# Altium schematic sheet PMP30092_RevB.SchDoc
size 431 x 279 mm; Date: Not shown in title block; ApprovedBy: Not shown in title block; CheckedBy: Not shown in title block; Author: Not shown in title block; CompanyName: Not shown in title block; Engineer: Not shown in title block; Organization: Not shown in title block; Address1: Not shown in title block; Address2: Not shown in title block; Address3: Not shown in title block; Address4: Not shown in title block; DocumentNumber: 1; Revision: Use project parameter SCH_Rev; SheetNumber: 2; SheetTotal: 3; PageSetup: Record=PageOptions¦CenterHorizontal=True¦CenterVertical=True¦PrintScale=1.00¦XCorrection=1.00¦YCorrection=1.00¦PrintKind=0¦BorderSize=5000000¦LeftOffset=0¦BottomOffset=0¦Orientation=2¦PaperLength=1000¦PaperWidth=1000¦Scale=100¦PaperSource=15¦PrintQuality=600¦MediaType=1¦DitherType=10¦PaperKind=Letter¦PrintScaleMode=1
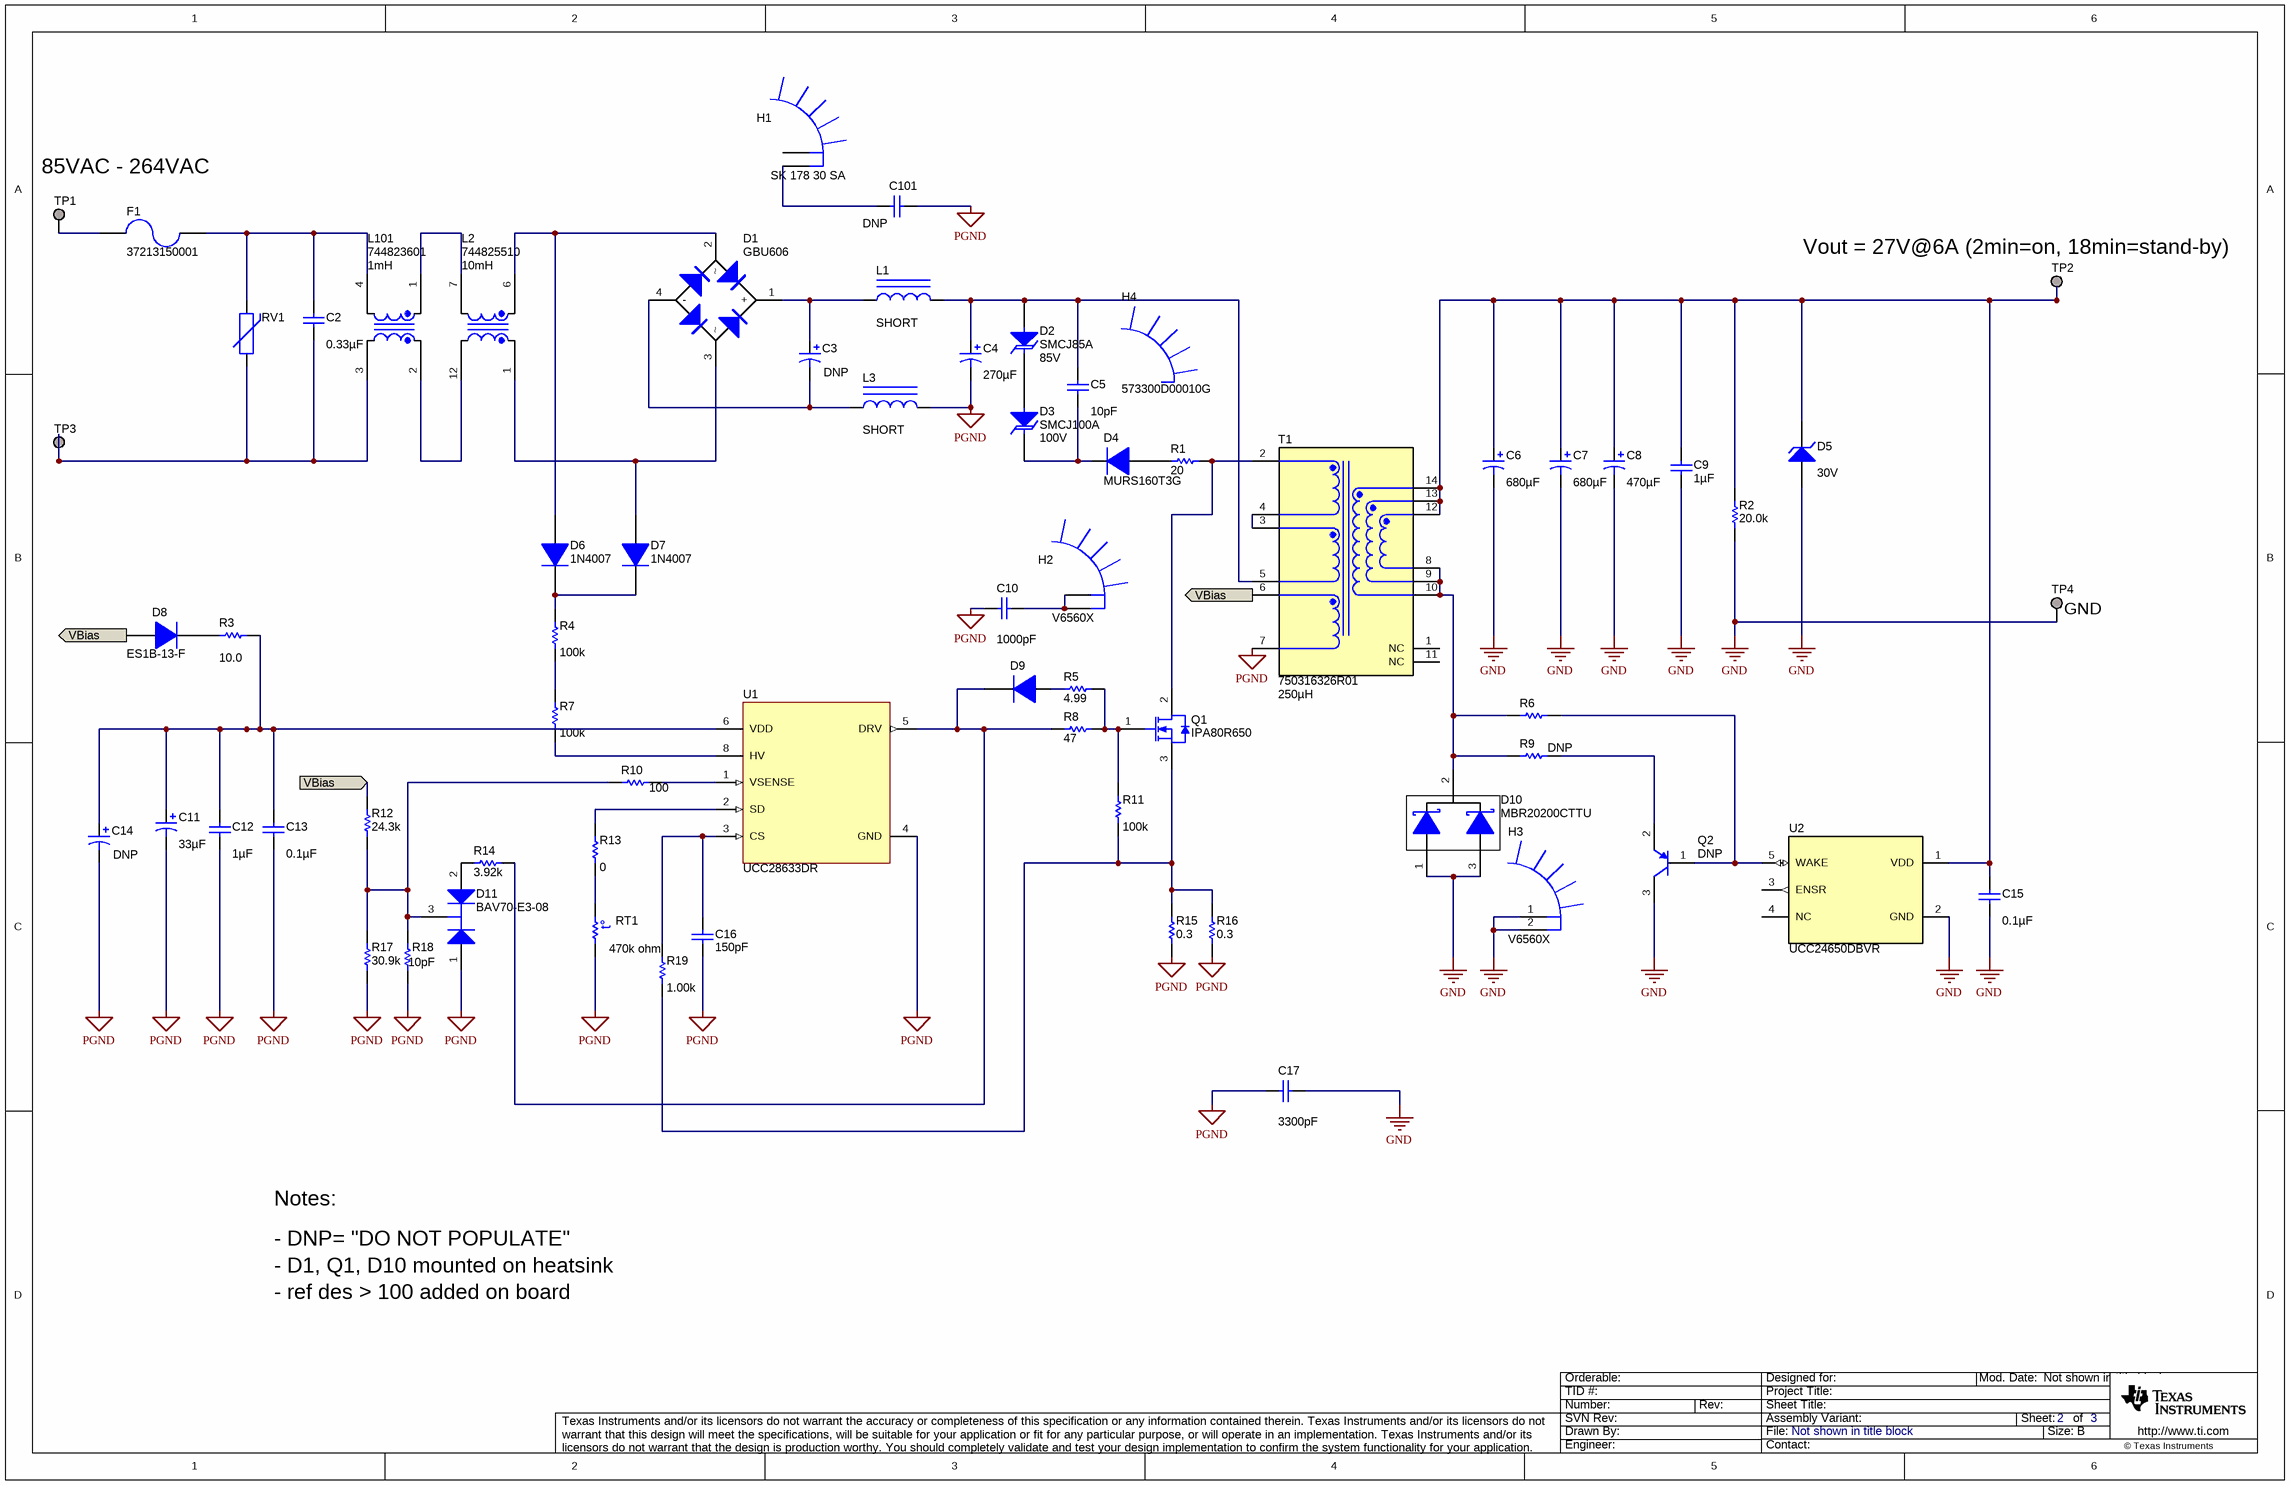
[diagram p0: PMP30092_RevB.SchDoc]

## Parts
C2  ValueDisplayed: 0.33µF  [B32922_14.5mm]  (hidden comment: B32922C3334M)
C3  DNP  [CY_1250x2000]
C4  ValueDisplayed: 270µF  [LGW_3000x3500]  (hidden comment: LGW2G271MELB35)
C5  ValueDisplayed: 10pF  [1206]  (hidden comment: 12062A100JAT2A)
C6  ValueDisplayed: 680µF  [HW_1000x2000]  (hidden comment: UHW1V681MPD6)
C7  ValueDisplayed: 680µF  [HW_1000x2000]  (hidden comment: UHW1V681MPD6)
C8  ValueDisplayed: 470µF  [HW_1000x1600]  (hidden comment: UHW1V471MPD)
C9  ValueDisplayed: 1µF  [1206_180]  (hidden comment: C3216X7R1H105K160AB)
C10  ValueDisplayed: 1000pF  [1206]  (hidden comment: GRM31BR72J102KW01L)
C11  ValueDisplayed: 33µF  [SM_RADIAL_E]  (hidden comment: EEE-FC1V330P)
C12  ValueDisplayed: 1µF  [1206]  (hidden comment: C1206C105K3RACTU)
C13  ValueDisplayed: 0.1µF  [0603]  (hidden comment: 06035C104KAT2A)
C14  value DNP  [SM_RADIAL_E]  (hidden comment: Used in BOM report)
C15  ValueDisplayed: 0.1µF  [0805_HV]  (hidden comment: 08055C104KAT2A)
C16  ValueDisplayed: 150pF  [0603]  (hidden comment: C0603C151J5GACTU)
C17  ValueDisplayed: 3300pF  [KX_1000x700]  (hidden comment: DE1E3KX332MN4AP01F)
C101  value DNP  [1206]  (hidden comment: GRM31BR72J102KW01L)
D1  GBU606  [GBU]
D2  SMCJ85A  value 85V  [SMC]
D3  SMCJ100A  value 100V  [SMC]
D4  MURS160T3G  [SMB]
D5  value 30V  [SOD-123]  (hidden comment: MMSZ5255B-7-F)
D6  1N4007  [DO-41]
D7  1N4007  [DO-41]
D8  ES1B-13-F  [SMA]
D9  BAS316,115  [sod-323]  (value not drawn)
D10  MBR20200CTTU  [TO-220AB]
D11  BAV70-E3-08  [SOT-23]
F1  37213150001  [FUSE_372]
H1  SK 178 30 SA
H2  V6560X  [ASMN_V6560X]
H3  V6560X  [ASMN_V6560X]
H4  573300D00010G  [HEATSINK_573300D00010G]
L1  ValueDisplayed: SHORT  [DO5040H]  (hidden comment: DO5040H-473MLB)
L2  744825510  ValueDisplayed: 10mH  [WE-CMB_XL]
L3  ValueDisplayed: SHORT  [DO5040H]  (hidden comment: DO5040H-473MLB)
L101  744823601  value 1mH  [WE-CMB_M]
Q1  IPA80R650  [TO-220AB]
Q2  DNP  [SOT-23]
R1  ValueDisplayed: 20  [2512]  (hidden comment: CRCW251220R0JNEG)
R2  ValueDisplayed: 20.0k  [0603]  (hidden comment: RC0603FR-0720KL)
R3  ValueDisplayed: 10.0  [0805_HV]  (hidden comment: CRCW080510R0FKEA)
R4  ValueDisplayed: 100k  [1206]  (hidden comment: CRCW1206100KFKEA)
R5  ValueDisplayed: 4.99  [0805_HV]  (hidden comment: RC0805FR-074R99L)
R6  CRCW08050000Z0EA  [0805_HV]  (value not drawn)
R7  ValueDisplayed: 100k  [1206]  (hidden comment: CRCW1206100KFKEA)
R8  ValueDisplayed: 47  [0805_HV]  (hidden comment: ERJ-6GEYJ470V)
R9  DNP  [0805_HV]
R10  ValueDisplayed: 100  [0603]  (hidden comment: CRCW0603100RFKEA)
R11  ValueDisplayed: 100k  [0603]  (hidden comment: CRCW0603100KFKEA)
R12  ValueDisplayed: 24.3k  [0603]  (hidden comment: CRCW060324K3FKEA)
R13  ValueDisplayed: 0  [0603]  (hidden comment: CRCW06030000Z0EA)
R14  ValueDisplayed: 3.92k  [0603]  (hidden comment: CRCW06033K92FKEA)
R15  ValueDisplayed: 0.3  [2512]  (hidden comment: CSRN2512FKR300)
R16  ValueDisplayed: 0.3  [2512]  (hidden comment: CSRN2512FKR300)
R17  ValueDisplayed: 30.9k  [0603]  (hidden comment: CRCW060330K9FKEA)
R18  value 10pF  [0603]  (hidden comment: Used in BOM report)
R19  ValueDisplayed: 1.00k  [0603]  (hidden comment: CRCW06031K00FKEA)
RT1  value 470k ohm  [0603]  (hidden comment: NCP18WM474J03RB)
RV1  B72214S0271K101  [VAR_B72214S0271]  (value not drawn)
T1  750316326R01  ValueDisplayed: 250µH  [Wurth_750316326]
TP1  Suggest using a net name here  [Keystone1503-2]  (value not drawn)
TP2  Suggest using a net name here  [Keystone1503-2]  (value not drawn)
TP3  Suggest using a net name here  [Keystone1503-2]  (value not drawn)
TP4  Suggest using a net name here  [Keystone1503-2]  (value not drawn)
U1  UCC28633DR  [D0007A_N]
U2  UCC24650DBVR  [DBV0005A_N]

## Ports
VBias, VBias (in)

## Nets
GND: C6.2(-) C7.2(-) C8.2(-) C9.2 C15.2 C17.1 D5.2(A) D10.1(A) D10.3(A) H3.1 H3.2 Q2.3(C) R2.1 TP4.1 U2.2(GND)
PGND: C4.2(-) C10.2 C11.2(-) C12.2 C13.2 C14.2(-) C16.2 C17.2 C101.1 D11.1(A) L3.2 R15.1 R16.1 R17.1 R18.1 RT1.1 T1.7 U1.4(GND)
VBias: D8.2(A) R12.2 T1.6 ; port VBias
NetC2_1: C2.1 F1.1 L101.4 RV1.2
NetC2_2: C2.2 L101.3 RV1.1 TP3.1
NetC3_1: C3.1(+) D1.1(+) L1.1
NetC3_2: C3.2(-) D1.4(-) L3.1
NetC4_1: C4.1(+) C5.1 D2.2(A) L1.2 T1.5
NetC5_2: C5.2 D3.1(K) D4.1(K)
NetC6_1: C6.1(+) C7.1(+) C8.1(+) C9.1 C15.1 D5.1(K) R2.2 T1.12 T1.13 T1.14 TP2.1 U2.1(VDD)
NetC10_1: C10.1 H2.1 H2.2
NetC11_1: C11.1(+) C12.1 C13.1 C14.1(+) R3.2 U1.6(VDD)
NetC16_1: C16.1 R19.2 U1.3(CS)
NetC101_2: C101.2 H1.2
NetD1_2: D1.2 D6.2(A) L2.6
NetD1_3: D1.3 D7.2(A) L2.1
NetD2_1: D2.1(K) D3.2(A)
NetD4_2: D4.2(A) R1.1
NetD6_1: D6.1(K) D7.1(K) R4.2
NetD8_1: D8.1(K) R3.1
NetD9_1: D9.1(K) R8.1 R14.2 U1.5(DRV)
NetD9_2: D9.2(A) R5.1
NetD10_2: D10.2(K) R6.1 R9.1 T1.8 T1.9 T1.10
NetD11_2: D11.2(K) R14.1
NetD11_3: D11.3(C) R10.1 R12.1 R17.2 R18.2
NetF1_2: F1.2 TP1.1
NetL2_7: L2.7 L101.1
NetL2_12: L2.12 L101.2
NetQ1_1: Q1.1(G) R5.2 R8.2 R11.2
NetQ1_2: Q1.2(D) R1.2 T1.2
NetQ1_3: Q1.3(S) R11.1 R15.2 R16.2 R19.1
NetQ2_1: Q2.1(B) R6.2 U2.5(WAKE)
NetQ2_2: Q2.2(E) R9.2
NetR4_1: R4.1 R7.2
NetR7_1: R7.1 U1.8(HV)
NetR10_2: R10.2 U1.1(VSENSE)
NetR13_1: R13.1 RT1.2
NetR13_2: R13.2 U1.2(SD)
NetT1_3: T1.3 T1.4

Not connected (* = marked no-connect by the designer): H1 1; T1 1(NC) 11(NC); U2 3(ENSR) 4(NC)

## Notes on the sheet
- 85VAC - 264VAC
- (near TP2) Vout = 27V@6A (2min=on, 18min=stand-by)
- (near T1) Nsec
- (near TP4) GND
- Notes:
- - DNP= "DO NOT POPULATE"
- - D1, Q1, D10 mounted on heatsink
- - ref des > 100 added on board

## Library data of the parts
C2 = B32922C3334M: CAP, Film, 0.33 µF, 630 V, +/- 20%, TH; Manufacturer: TDK; Polarized: N; CompType: Capacitor; Value: 0.33uF; U/M: EA; Cap_F: 0.00000033; Tolerance_%: 20; Value1: Unknown; VDC_V: 630; Value2: 630V; TaMax_C: 110; AEC Category: Q200
C3 = UCY2G270MHD1TO: CAP, AL, 27 µF, 400 V, +/- 20%, TH; Manufacturer: Nichicon; Polarized: Y; CompType: Capacitor; U/M: EA; Cap_F: 0.000027; Tolerance_%: 20; Value1: Unknown; VDC_V: 400; Value2: 400V; IRMS_A: 0.36; TaMin_C: -40; TaMax_C: 105; Cap_Case: 12.5x20; AEC Category: Q200; AEC Qualified: N; Lifetime @ Temp.: 12000 Hrs @ 105°C; Polarization: Polar; Ripple Current: 235mA @ 120Hz
C4 = LGW2G271MELB35: CAP, AL, 270 µF, 400 V, +/- 20%, TH; Manufacturer: Nichicon; Polarized: Y; CompType: Capacitor; Value: 270uF; U/M: EA; Cap_F: 0.00027; Tolerance_%: 20; Value1: Unknown; VDC_V: 400; Value2: 400V; IRMS_A: 2.12; TaMin_C: -25; TaMax_C: 105; Cap_Case: 30x35mm; AEC Category: Q200; AEC Qualified: N
C5 = 12062A100JAT2A: CAP, CERM, 10 pF, 200 V, +/- 5%, C0G/NP0, 1206; Manufacturer: AVX; Polarized: N; CompType: Capacitor; Value: 10pF; U/M: EA; Cap_F: 0.00000000001; Tolerance_%: 5; Value1: Unknown; VDC_V: 200; Value2: 200V; TaMin_C: -55; TaMax_C: 125; AEC Category: Q200
C6 C7 = UHW1V681MPD6: CAP, AL, 680 µF, 35 V, +/- 20%, 0.019 ohm, TH; Manufacturer: Nichicon; Polarized: Y; CompType: Capacitor; Value: 680uF; U/M: EA; Cap_F: 0.00068; Tolerance_%: 20; VDC_V: 35; Value2: 35V; ESR_ohm: 0.019; IRMS_A: 2.5; TaMin_C: -40; TaMax_C: 105; Cap_Case: 10x20; AEC Category: Q200; AEC Qualified: N
C8 = UHW1V471MPD: CAP, AL, 470 µF, 35 V, +/- 20%, 0.03 ohm, TH; Manufacturer: Nichicon; Polarized: Y; CompType: Capacitor; Value: 470uF; U/M: EA; Cap_F: 0.00047; Tolerance_%: 20; VDC_V: 35; Value2: 35V; ESR_ohm: 0.03; IRMS_A: 2; TaMin_C: -40; TaMax_C: 105; Cap_Case: 10x16mm; AEC Category: Q200; AEC Qualified: N
C9 = C3216X7R1H105K160AB: CAP, CERM, 1 µF, 50 V, +/- 10%, X7R, 1206; Manufacturer: TDK; Polarized: N; CompType: Capacitor; Value: 1uF; U/M: EA; Cap_F: 0.000001; Tolerance_%: 10; ESR_ohm: 0.009289; Value1: 0.009289 ohm; VDC_V: 50; Value2: 50V; IRMS_A: 2.38446; TaMin_C: -55; TaMax_C: 125; SizeArea_mm2: 5.12; SizeAreaWB_mm2: 10.92; SizeX_mm: 3.2; SizeY_mm: 1.6; SizeZ_mm: 1.8; AEC Category: Q200
C10 = GRM31BR72J102KW01L: CAP, CERM, 1000 pF, 630 V, +/- 10%, X7R, 1206; Manufacturer: MuRata; Polarized: N; CompType: Capacitor; Value: 1000pF; U/M: EA; Cap_F: 0.000000001; Tolerance_%: 10; Value1: Unknown; VDC_V: 630; Value2: 630V; TaMin_C: -55; TaMax_C: 125; SizeArea_mm2: 5.12; SizeAreaWB_mm2: 10.92; SizeX_mm: 3.2; SizeY_mm: 1.6; SizeZ_mm: 1.35; AEC Category: Q200
C11 = EEE-FC1V330P: CAP, AL, 33 µF, 35 V, +/- 20%, 0.4 ohm, SMD; Manufacturer: Panasonic; Polarized: Y; CompType: Capacitor; Value: 33uF; U/M: EA; Cap_F: 0.000033; Tolerance_%: 20; Value1: 0.4 ohm; VDC_V: 35; Value2: 35V; ESR_ohm: 0.4; IRMS_A: 0.15; TaMin_C: -40; TaMax_C: 105; Cap_Case: E; AEC Category: Q200
C12 = C1206C105K3RACTU: CAP, CERM, 1 µF, 25 V, +/- 10%, X7R, 1206; Manufacturer: Kemet; Polarized: N; CompType: Capacitor; Value: 1uF; U/M: EA; Cap_F: 0.000001; Tolerance_%: 10; ESR_ohm: 0.011; Value1: 0.011 ohm; VDC_V: 25; Value2: 25V; IRMS_A: 3.55; TaMin_C: -55; TaMax_C: 125; AEC Category: Q200
C13 = 06035C104KAT2A: CAP, CERM, 0.1 µF, 50 V, +/- 10%, X7R, 0603; Manufacturer: AVX; Polarized: N; CompType: Capacitor; Value: 0.1uF; U/M: EA; Cap_F: 0.0000001; Tolerance_%: 10; Value1: Unknown; VDC_V: 50; Value2: 50V; TaMin_C: -55; TaMax_C: 125; AEC Category: Q200
C14 = Capacitor_Polarized: CAP, [Technology], xxxF, xxV, +/-xx%, xxOhm ESR, [MountType]; Polarized: Y; U/M: EA
C15 = 08055C104KAT2A: CAP, CERM, 0.1 µF, 50 V, +/- 10%, X7R, 0805; Manufacturer: AVX; Polarized: N; CompType: Capacitor; Value: 0.1uF; U/M: EA; Cap_F: 0.0000001; Tolerance_%: 10; ESR_ohm: 0.024; Value1: 0.024 ohm; VDC_V: 50; Value2: 50V; TaMin_C: -55; TaMax_C: 125; Cap_Case: 0805; SizeArea_mm2: 2.5; SizeAreaWB_mm2: 6.75; SizeX_mm: 2; SizeY_mm: 1.25; SizeZ_mm: 1.45; AEC Category: Q200
C16 = C0603C151J5GACTU: CAP, CERM, 150 pF, 50 V, +/- 5%, C0G/NP0, 0603; Manufacturer: Kemet; Polarized: N; CompType: Capacitor; Value: 150pF; U/M: EA; Cap_F: 0.00000000015; Tolerance_%: 5; Value1: Unknown; VDC_V: 50; Value2: 50V; TaMin_C: -55; TaMax_C: 125; AEC Category: Q200; SizeArea_mm2: 1.28; SizeAreaWB_mm2: 4.68; SizeX_mm: 1.6; SizeY_mm: 0.8; SizeZ_mm: 1
C17 = DE1E3KX332MN4AP01F: CAP, CERM, 3300 pF, 300 V, +/- 20%, E, D10xT7mm; Manufacturer: MuRata; Polarized: N; CompType: Capacitor; Value: 3300pF; U/M: EA; Cap_F: 0.0000000033; Tolerance_%: 20; Value1: Unknown; VDC_V: 300; Value2: 300V; TaMin_C: -40; TaMax_C: 125; Cap_Case: 10x7mm; SizeArea_mm2: 70; SizeAreaWB_mm2: 108; SizeX_mm: 10; SizeY_mm: 7; SizeZ_mm: 13; AEC Category: Q200
C101 = GRM31BR72J102KW01L: CAP, CERM, 1000 pF, 630 V, +/- 10%, X7R, 1206; Manufacturer: MuRata; Polarized: N; CompType: Capacitor; ValueDisplayed: 1000pF; U/M: EA; Cap_F: 0.000000001; Tolerance_%: 10; Value1: Unknown; VDC_V: 630; Value2: 630V; TaMin_C: -55; TaMax_C: 125; SizeArea_mm2: 5.12; SizeAreaWB_mm2: 10.92; SizeX_mm: 3.2; SizeY_mm: 1.6; SizeZ_mm: 1.35; AEC Category: Q200
D1 = GBU606: Diode, Switching-Bridge, 600 V, 6 A, TH; Manufacturer: Diodes Inc.; U/M: EA; Vf_V: 1; Value: 600V; Value1: 6A; Value2: 1V; Io_A: 6; Vr_V: 600; TJmax_C: 150; RJC_CperW: 2.2; AEC Category: Q101; AEC Qualified: N
D2 = SMCJ100A: Diode, TVS, Uni, 85 V, 1500 W, SMC; Manufacturer: Littelfuse; U/M: EA; Power_W: 1500; Vr_V: 100; Value1: 1500W; RJA_CperW: 75; SizeAreaWB_mm2: 83.2686; SizeArea_mm2: 50.5686; SizeX_mm: 8.13; SizeY_mm: 6.22; SizeZ_mm: 2.6; AEC Category: Q101
D3 = SMCJ100A: Diode, TVS, Uni, 100 V, 1500 W, SMC; Manufacturer: Littelfuse; U/M: EA; Power_W: 1500; Vr_V: 100; Value1: 1500W; RJA_CperW: 75; SizeAreaWB_mm2: 83.2686; SizeArea_mm2: 50.5686; SizeX_mm: 8.13; SizeY_mm: 6.22; SizeZ_mm: 2.6; AEC Category: Q101
D4 = MURS160T3G: Diode, Ultrafast, 600 V, 2 A, SMB; Manufacturer: ON Semiconductor; U/M: EA; Vf_V: 1.25; Value: 600V; Value1: 2A; Value2: 1.25V; Io_A: 2; Vr_V: 600; TJmax_C: 175; AEC Category: Q101
D5 = MMSZ5255B-7-F: Diode, Zener, 30 V, 500 mW, SOD-123; Manufacturer: Diodes Inc.; SymbolCreator: a0412235; U/M: EA; Power_W: 0.5; Vz_V: 30; Value1: 0.5W; RJA_CperW: 350; SizeAreaWB_mm2: 13.095; SizeArea_mm2: 6.545; SizeX_mm: 3.85; SizeY_mm: 1.7; SizeZ_mm: 1.35; AEC Category: Q101
D6 D7 = 1N4007: Diode, P-N, 1000 V, 1 A, TH; Manufacturer: Fairchild Semiconductor; U/M: EA; Vf_V: 1.1; Value: 1000V; Value1: 1A; Value2: 1.1V; Io_A: 1; Vr_V: 1000; TJmax_C: 175; RJC_CperW: 50; AEC Category: Q101
D8 = ES1B-13-F: Diode, Superfast Rectifier, 100 V, 1 A, SMA; Manufacturer: Diodes Inc.; U/M: EA; Vf_V: 0.92; Value: 100V; Value1: 1A; Value2: 0.92V; Io_A: 1; Vr_V: 100; TJmax_C: 150; RJC_CperW: 25; SizeAreaWB_mm2: 37.3428; SizeArea_mm2: 16.3228; SizeX_mm: 5.59; SizeY_mm: 2.92; SizeZ_mm: 2.87; AEC Category: Q101
D9 = BAS316,115: Diode, Ultrafast, 100 V, 0.25 A, SOD-323; Manufacturer: NXP Semiconductor; U/M: EA; Vf_V: 1.4; Value1: 0.25A; Value2: 1.4V; Io_A: 0.25; Vr_V: 100; TJmax_C: 150; AEC Category: Q101
D10 = MBR20200CTTU: Diode, Schottky, 200 V, 10 A, TH; Manufacturer: Fairchild Semiconductor; SymbolCreator: a0411947; U/M: EA; Vf_V: 0.9; Value: 200V; Value1: 10A; Value2: 0.9V; Io_A: 10; Vr_V: 200; TJmax_C: 150; RJC_CperW: 1.5; SizeAreaWB_mm2: 397.048; SizeArea_mm2: 312.208; SizeX_mm: 30.02; SizeY_mm: 10.4; SizeZ_mm: 4.82; AEC Category: Q101; AEC Qualified: N
D11 = BAV70-E3-08: Diode, Switching, 70 V, 0.25 A, AEC-Q101, SOT-23; Manufacturer: Vishay-Semiconductor; SymbolCreator: a0412235; U/M: EA; Vf_V: 1.25; Value: 70V; Value1: 0.25A; Value2: 1.25V; Io_A: 0.25; Vr_V: 70; TJmax_C: 150; AEC Category: Q101; AEC Qualified: Y
F1 = 37213150001: Fuse, 3.15 A, 250VAC/VDC, TH; Manufacturer: Littelfuse; VDC_V: 250; Irating_A: 3.15
H1 = V6560X: HEATSINK, Fischer, 7K/W
H2 H3 = V6560X: HEATSINK, ALUM, ANOD, for TO-220; Manufacturer: Assman WSW; SymbolCreator: a0799628
H4 = 573300D00010G: Heatsink, DDPAK/TO-263, SMT; Manufacturer: Aavid; SymbolCreator: a0412235
L1 L3 = DO5040H-473MLB: Inductor, Drum Core, Ferrite, 47 µH, 3.7 A, 0.05 ohm, SMD; Manufacturer: Coilcraft; Value: 47uH; Ind_H: 47.0E-6; Imax_A: 3.7; Irms: 3.7A @ 40C rise; Isat: 7.8A @ 10% inductance drop; DCR_ohm: 0.05; Value2: 3.7A; AEC Category: Q200
L2 = 744825510: Coupled inductor, 10 mH, 5 A, 0.055 ohm, TH; Manufacturer: Wurth Elektronik; SymbolCreator: a0799628; Value: 10mH; Ind_H: 10.0E-3; DCR_ohm: 0.055
L101 = 744823601: Coupled inductor, 1 mH, 6 A, 0.013 ohm, TH; Manufacturer: Wurth Elektronik; SymbolCreator: a0799628; Ind_H: 1.0E-6; DCR_ohm: 0.013
Q1 = SPP06N80C3: MOSFET, N-CH, 800 V, TO-220AB; Manufacturer: Infineon Technologies; Alternate Manufacturer: None; U/M: EA; ChType: N; Value: 800V; VdsMax_V: 800; Rdson45_ohm: 0.9; Value2: 41 nC; QgTyp_nC: 41; Vgs_V: 3.9; IdsMax_A: 6; SizeAreaWB_mm2: 397.048; SizeArea_mm2: 312.208; SizeX_mm: 30.02; SizeY_mm: 10.4; SizeZ_mm: 4.82; AEC Category: Q101; FET Type: MOSFET N-Channel, Metal Oxide; FET Feature: Standard; Current - Continuous Drain (Id) @ 25°C: 4.5A (Tc); Rds On (Max) @ Id, Vgs: 650 mOhm @ 5.1A, 10V; Gate Charge (Qg) @ Vgs: 45nC @ 10V; Input Capacitance (Ciss) @ Vds: 1100pF @ 100V; Power - Max: 33W
Q2 = MMBT5401LT1G, ON Semiconductor: Transistor, PNP, 150 V, 0.5 A, SOT-23; CompType: BJT; PNP: 1; NPN: 0; Vceo_V: 150; Vcesat1_V: 0.5; Value1: 0.5 A; HfeMax: 240; TaMin_C: -55; U/M: EA; AEC Category: Q101
R1 = CRCW251220R0JNEG: RES, 20, 5%, 1 W, AEC-Q200 Grade 0, 2512; Manufacturer: Vishay-Dale; CompType: Resistor; Value: 20; Value_Code: 20R0; Tolerance_%: 5; Power_W: 1; Value2: 1W; VDC_V: 500; TempCo: 200 ppm/C; SizeArea_mm2: 20.16; SizeX_mm: 6.3; SizeY_mm: 3.2; SizeZ_mm: 0.71; EIA_Code: E24; U/M: EA; AEC Category: Q200; AEC Qualified: Y; AEC Grade: 0
R2 = RC0603FR-0720KL: RES, 20.0 k, 1%, 0.1 W, 0603; Manufacturer: Yageo America; CompType: Resistor; Value: 20.0k; Res_ohm: 20000; Value_Code: 20k0; Tolerance_%: 1; Power_W: 0.1; Value2: 0.1W; VDC_V: 150; TempCo: 200 ppm/C; SizeArea_mm2: 1.28; SizeX_mm: 1.6; SizeY_mm: 0.8; EIA_Code: E96; U/M: EA; AEC Category: Q200
R3 = CRCW080510R0FKEA: RES, 10.0, 1%, 0.125 W, 0805; Manufacturer: Vishay-Dale; CompType: Resistor; Value: 10.0; Res_ohm: 10; Value_Code: 10R0; Tolerance_%: 1; Power_W: 0.125; Value2: 0.125W; VDC_V: 150; TempCo: 100 ppm/C; SizeArea_mm2: 2.5; SizeX_mm: 2; SizeY_mm: 1.25; SizeZ_mm: 1.45; EIA_Code: E96; U/M: EA; AEC Category: Q200
R4 R7 = CRCW1206100KFKEA: RES, 100 k, 1%, 0.25 W, 1206; Manufacturer: Vishay-Dale; CompType: Resistor; Value: 100k; Res_ohm: 100000; Tolerance_%: 1; Power_W: 0.25; Value2: 0.25W; VDC_V: 200; TempCo: 100 ppm/C; EIA_Code: E96; U/M: EA; AEC Category: Q200
R5 = RC0805FR-074R99L: RES, 4.99, 1%, 0.125 W, 0805; Manufacturer: Yageo America; CompType: Resistor; Value: 4.99; Value_Code: 4R99; Tolerance_%: 1; Power_W: 0.125; Value2: 0.125W; VDC_V: 150; TempCo: 200 ppm/C; EIA_Code: E96; U/M: EA; AEC Category: Q200; SizeArea_mm2: 2.5; SizeX_mm: 2; SizeY_mm: 1.25; SizeZ_mm: 1.45
R6 = CRCW08050000Z0EA: RES, 0, 5%, 0.125 W, 0805; Manufacturer: Vishay-Dale; CompType: Resistor; Value: 1k; Res_ohm: 0; Value_Code: 0000; Tolerance_%: 5; Power_W: 0.125; Value2: 0.125W; VDC_V: 150; TempCo: 200 ppm/C; SizeArea_mm2: 2.5; SizeX_mm: 2; SizeY_mm: 1.25; SizeZ_mm: 1.45; EIA_Code: E24; U/M: EA; AEC Category: Q200
R8 = ERJ-6GEYJ470V: RES, 47, 5%, 0.125 W, 0805; Manufacturer: Panasonic; CompType: Resistor; Value: 47; Value_Code: 47R0; Tolerance_%: 5; Power_W: 0.125; Value2: 0.125W; VDC_V: 150; TempCo: 200 ppm/C; EIA_Code: E24; U/M: EA; AEC Category: Q200; SizeArea_mm2: 2.5; SizeX_mm: 2; SizeY_mm: 1.25; SizeZ_mm: 1.45
R9 = CRCW0805100RFKEA: RES, 100, 1%, 0.125 W, 0805; Manufacturer: Vishay-Dale; CompType: Resistor; ValueDisplayed: 100; Value_Code: 100R; Tolerance_%: 1; Power_W: 0.125; Value2: 0.125W; VDC_V: 150; TempCo: 100 ppm/C; SizeArea_mm2: 2.5; SizeX_mm: 2; SizeY_mm: 1.25; SizeZ_mm: 1.45; EIA_Code: E96; U/M: EA; AEC Category: Q200
R10 = CRCW0603100RFKEA: RES, 100, 1%, 0.1 W, 0603; Manufacturer: Vishay-Dale; CompType: Resistor; Value: 100; Value_Code: 100R; Tolerance_%: 1; Power_W: 0.1; Value2: 0.1W; VDC_V: 75; TempCo: 100 ppm/C; EIA_Code: E96; U/M: EA; AEC Category: Q200
R11 = CRCW0603100KFKEA: RES, 100 k, 1%, 0.1 W, 0603; Manufacturer: Vishay-Dale; CompType: Resistor; Value: 100k; Res_ohm: 100000; Tolerance_%: 1; Power_W: 0.1; Value2: 0.1W; VDC_V: 75; TempCo: 100 ppm/C; EIA_Code: E96; U/M: EA; AEC Category: Q200
R12 = CRCW060324K3FKEA: RES, 24.3 k, 1%, 0.1 W, 0603; Manufacturer: Vishay-Dale; CompType: Resistor; Value: 24.3k; Res_ohm: 24300; Value_Code: 24k3; Tolerance_%: 1; Power_W: 0.1; Value2: 0.1W; VDC_V: 75; TempCo: 100 ppm/C; EIA_Code: E96; U/M: EA; AEC Category: Q200; SizeArea_mm2: 1.28; SizeX_mm: 1.6; SizeY_mm: 0.8
R13 = CRCW06030000Z0EA: RES, 0, 5%, 0.1 W, 0603; Manufacturer: Vishay-Dale; CompType: Resistor; Value: 0; Value_Code: 0000; Tolerance_%: 5; Power_W: 0.1; Value2: 0.1W; VDC_V: 75; TempCo: 200 ppm/C; SizeArea_mm2: 1.28; SizeX_mm: 1.6; SizeY_mm: 0.8; SizeZ_mm: 1; EIA_Code: E24; U/M: EA; AEC Category: Q200
R14 = CRCW06033K92FKEA: RES, 3.92 k, 1%, 0.1 W, 0603; Manufacturer: Vishay-Dale; CompType: Resistor; Value: 3.92k; Res_ohm: 3920; Value_Code: 3k92; Tolerance_%: 1; Power_W: 0.1; Value2: 0.1W; VDC_V: 75; TempCo: 100 ppm/C; EIA_Code: E96; U/M: EA; AEC Category: Q200
R15 R16 = CSRN2512FKR300: RES, 0.3, 1%, 2 W, 2512; Manufacturer: Stackpole Electronics Inc; CompType: Resistor; Value: 0.3; Value_Code: R300; Tolerance_%: 1; Power_W: 2; Value2: 2W; TempCo: 200 ppm/C; EIA_Code: E96; U/M: EA; AEC Category: Q200; SizeArea_mm2: 20.16; SizeX_mm: 6.3; SizeY_mm: 3.2; SizeZ_mm: 0.71
R17 = CRCW060330K9FKEA: RES, 30.9 k, 1%, 0.1 W, 0603; Manufacturer: Vishay-Dale; CompType: Resistor; Value: 30.9k; Res_ohm: 30900; Value_Code: 30k9; Tolerance_%: 1; Power_W: 0.1; Value2: 0.1W; VDC_V: 75; TempCo: 100 ppm/C; EIA_Code: E96; U/M: EA; AEC Category: Q200; SizeArea_mm2: 1.28; SizeX_mm: 1.6; SizeY_mm: 0.8
R18 = Resistor: Cap, COG, 0603; U/M: EA
R19 = CRCW06031K00FKEA: RES, 1.00 k, 1%, 0.1 W, 0603; Manufacturer: Vishay-Dale; CompType: Resistor; Value: 1.00k; Res_ohm: 1000; Value_Code: 1k00; Tolerance_%: 1; Power_W: 0.1; Value2: 0.1W; VDC_V: 75; TempCo: 100 ppm/C; EIA_Code: E96; U/M: EA; AEC Category: Q200
RT1 = NCP18WM474J03RB: Thermistor NTC, 470k ohm, 5%, 0603; Manufacturer: MuRata; Tolerance_%: 5; Power_W: 0.1; TaMin_C: -40; TaMax_C: 125; U/M: EA
RV1 = B72214S0271K101: Varistor, 430V, 4.5KA, TH; Manufacturer: TDK; SymbolCreator: a0412235
T1 = 750316326: Transformer, 250 uH, TH; Manufacturer: Wurth Elektronik; SymbolCreator: Altium; Value: 250uH; Lp: 250; DCR_ohm: 0.17; Ns1toNp: 4; Rs1: 0.01; SizeAreaWB_mm2: 1771; SizeArea_mm2: 1606; SizeX_mm: 44; SizeY_mm: 36.5; SizeZ_mm: 28.5
TP1-TP4 = 1503-2: Terminal, Turret, TH, Double; Manufacturer: Keystone; CompType: Turret Terminal
U1 = UCC28633DR: High-Power Flyback Controller with Primary-Side Regulation and Peak-Power Mode, D0007A; Manufacturer: Texas Instruments; SymbolCreator: Altium; CompType: IC; U/M: EA
U2 = UCC24650DBVR: 200-V Wake-Up Monitor for Fast Transient PSR, DBV0005A; Alternate PartNumber: UCC24650DBVT; Manufacturer: Texas Instruments; SymbolCreator: x0208326; CompType: IC; U/M: EA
